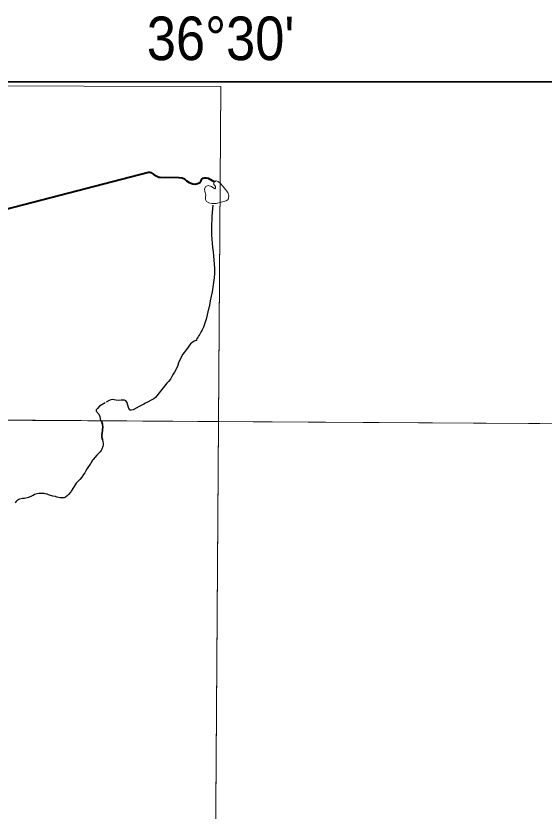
# Model space of a CAD drawing. Extents: x 553962 to 842807, y 8883888 to 9032388.
# Drawn here: x 616310 to 622374, y 8916398 to 8925528 of the extents above; entities that cross this region are included whole.
import ezdxf
from ezdxf.enums import TextEntityAlignment as Align

# ---------------------------------------------------------------- set-up
doc = ezdxf.new("R2010")
doc.units = 0
doc.header["$LTSCALE"] = 20
doc.layers.add('6', color=7, linetype='Continuous', lineweight=13)

msp = doc.modelspace()

# ---------------------------------------------------------------- linework, layer by layer
at = {"layer": '6', "lineweight": 35}
msp.add_lwpolyline([(574695.3, 8924769.57), (626625.69, 8924769.57), (626625.69, 8896026.67), (574695.3, 8896026.67)], close=True, dxfattribs=at)
at = {"layer": '6'}
for points in [[(607657.67, 8924743.35), (618662.98, 8924716.12), (618635.99, 8920869.64), (607600.79, 8920952.39)], [(618590.4, 8923622.56), (618579.89, 8923599.16), (618603.3, 8923569.07), (618601.86, 8923549.97), (618595.18, 8923541.37), (618555.06, 8923567.64), (618516.37, 8923579.58), (618490.11, 8923569.07), (618473.87, 8923540.42), (618479.6, 8923509.85), (618492.02, 8923472.6), (618488.2, 8923448.24), (618485.81, 8923418.63), (618496.79, 8923398.57), (618526.4, 8923383.29), (618561.27, 8923372.78), (618609.98, 8923374.21), (618666.82, 8923390.93), (618723.65, 8923405.74), (618745.62, 8923421.02), (618754.22, 8923461.61), (618742.28, 8923501.73), (618701.68, 8923551.88), (618663.95, 8923597.73), (618633.86, 8923625.43), (618610.46, 8923632.59)], [(618635.99, 8920869.64), (626625.69, 8920820.54), (626625.69, 8909822.11), (618558.68, 8909851.16)]]:
    msp.add_lwpolyline(points, close=True, dxfattribs=at)
for points in [[(618662.98, 8924716.12), (618558.35, 8909803.66), (618456.51, 8896026.67)], [(574684.91, 8921064.73), (596639.85, 8920989.8), (607636.31, 8920937.24), (626625.69, 8920820.54)]]:
    msp.add_lwpolyline(points, dxfattribs=at)
at = {"layer": '6', "lineweight": 40}
msp.add_lwpolyline([(614964.25, 8922992.87), (617832.56, 8923732.56), (617846.73, 8923732.78), (617858.91, 8923730.95), (617871.21, 8923721.04), (617893.69, 8923707.25), (617921.26, 8923691.52), (617934.55, 8923682.63), (617949.81, 8923677.82), (617965.03, 8923676.04), (618178.77, 8923671.37), (618220.32, 8923669), (618246.82, 8923657.29), (618269.45, 8923633.39), (618301.13, 8923613.68), (618341.84, 8923600.18), (618367.24, 8923594.52), (618405.53, 8923607.26), (618420.58, 8923616.6), (618432.53, 8923630.94), (618446.36, 8923654.41), (618458.38, 8923663.7), (618473.47, 8923670), (618492.74, 8923668.29), (618517.1, 8923664.63), (618591.29, 8923622.31)], dxfattribs=at)
at = {"layer": '6', "lineweight": 25}
for points in [[(618385.79, 8921803.11), (618379.34, 8921802.58), (618357.21, 8921792.12), (618316.15, 8921761.14), (618268.47, 8921697.71), (618226.72, 8921644.48), (618197.2, 8921585.38), (618177.56, 8921543.63), (618163.97, 8921503.99), (618129.48, 8921438.75), (618113.65, 8921413.23), (618101.9, 8921385.75), (618086.13, 8921356.18), (618063.22, 8921330.55), (618043.24, 8921312.04), (617912.98, 8921148.23), (617894.99, 8921131.77), (617799.53, 8921081.73), (617778.41, 8921071.29), (617725.14, 8921044.16), (617655.83, 8921005.65), (617632.6, 8921001.24), (617620.46, 8921001.04), (617606.98, 8921022.06), (617592.1, 8921070.34), (617586.74, 8921090.47), (617572.31, 8921107.42), (617555.98, 8921116.26), (617517.51, 8921115.64), (617491.23, 8921112.19), (617455.75, 8921114.66), (617418.17, 8921122.14), (617399.98, 8921119.83), (617381.89, 8921110.45), (617345.81, 8921092.5)], [(617334.15, 8921086.13), (617270.41, 8921047.01), (617247.53, 8921019.35), (617230.53, 8921004.93), (617231.78, 8920988.78), (617263.66, 8920954.92), (617272.18, 8920926.75), (617283.04, 8920877.99)], [(617303, 8920665.45), (617309.32, 8920639.1), (617311.46, 8920622.33), (617313.47, 8920613.9), (617313.61, 8920598.46), (617309.37, 8920582.98), (617298.1, 8920552.05), (617290.18, 8920537.81), (617278.19, 8920522.27), (617239.53, 8920482.64), (617196.18, 8920434.99), (617188.48, 8920425.46), (617182.48, 8920416.18), (617169.69, 8920388.46), (617163.22, 8920380.52), (617127.84, 8920330.64), (617112.75, 8920304.88), (617101.52, 8920282.33), (617087.69, 8920260.74), (617065.5, 8920231.39), (617042.78, 8920204.7), (617013.05, 8920175.22), (617003.53, 8920164.67), (616988.6, 8920143.84), (616945.63, 8920070.1), (616939.64, 8920064.23), (616914.66, 8920032.8), (616900.47, 8920019.09), (616878.82, 8920003.53), (616863.45, 8919995.59), (616858.61, 8919994.46), (616837.8, 8919993.2), (616816.92, 8919996.35), (616783.4, 8920002.8), (616772.97, 8920006.62), (616763.53, 8920011.12), (616735.62, 8920015.46), (616683.57, 8920028.79), (616669.35, 8920035.2), (616647.72, 8920042.08), (616635, 8920043.9), (616602.24, 8920045.92), (616583.77, 8920046.3), (616574.08, 8920045.74), (616539.03, 8920038.23), (616522.95, 8920032.3), (616509.17, 8920023.18), (616495.47, 8920017.49)], [(616495.47, 8920017.49), (616453.33, 8919999.97), (616409.41, 8919988.89), (616397.46, 8919986.63), (616384.75, 8919985.38), (616353, 8919979.15), (616343.83, 8919975.8), (616333.61, 8919969.71), (616322.48, 8919960.42), (616311.13, 8919948.72), (616302.47, 8919938.12)]]:
    msp.add_lwpolyline(points, dxfattribs=at)
at = {"layer": '6', "lineweight": 35}
msp.add_lwpolyline([(617294.17, 8920878.4), (617302.42, 8920840.89), (617306.52, 8920803.07), (617306.1, 8920783.94), (617303.97, 8920766.24), (617295.21, 8920713.22), (617295.42, 8920693.58), (617300.52, 8920675.78), (617303, 8920665.45)], dxfattribs=at)
at = {"layer": '6', "lineweight": 25}
msp.add_spline([(618379.34, 8921802.58), (618451, 8921925.63), (618534.63, 8922201.75), (618593.17, 8922628.48), (618559.72, 8923013.37), (618576.44, 8923356.42)], degree=3, dxfattribs=at)

# ---------------------------------------------------------------- texts
at = {"layer": '6', "width": 0.9}
msp.add_text("36°30'", height=500, dxfattribs=at).set_placement((618660.05, 8925020.1), align=Align.CENTER)

doc.saveas('drawing.dxf')
